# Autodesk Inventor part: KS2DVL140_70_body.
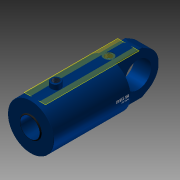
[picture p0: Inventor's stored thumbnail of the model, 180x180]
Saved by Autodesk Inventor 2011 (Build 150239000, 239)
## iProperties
Created: 2010-11
Document SubType Name: Modeling
Designer: TB
Mass: 405.061 g
Surface Area: 916.939 cm^2
Volume: 405.061 cm^3
Density: 1 g/cm^3
Author: TB
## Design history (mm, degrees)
sketch "Sketch2"
  geometry: L1 (-35, -3)-(-35, 3); L2 (-35, -9)-(-35, 9); L3 (-35, 0)-(-35, 82.5); L4 (-35, 82.5)-(-313, 82.5); L5 (-313, 82.5)-(-313, 82.5); L6 (-313, 82.5)-(-328, 82.5); L7 (-328, 82.5)-(-328, 39); L8 (-328, 39)-(-331, 36); L9 (-331, 36)-(-331, 35); L10 (-331, 35)-(-218, 35); L11 (-218, 35)-(-218, 70); L12 (-218, 70)-(-66, 70); L13 (-66, 70)-(-66, 0); L14 (-66, 0)-(-35, 0); L15 (-66, 0)-(-148.421, 0); L16 (-35, 9)-(-32, 12) reference; L17 (-32, 12)-(-35, 12) reference; L18 (-35, 12)-(-35, 9) reference; L19 (-32, 12)-(-35, 9) reference; L20 (-32, 12)-(-35, 12) reference; L21 (-35, 9)-(-35, 12) reference; L22 (-35, 9)-(-32, 12) reference; 1 further point
  constraints: 44 end point, 8 perpendicular, 6 parallel, 5 collinear, 2 horizontal, 2 vertical, 1 coincident, 1 midpoint, 1 point on line, 10 other
  dimensions: "DiaY" = 165 diameter of L4 L15; "DiaI" = 140 diameter of L12 L15; "d4" = 1 distance of L8.end L9.end; "d5" = 45 deg angle of L10 L8; "d6" = 3 distance between parallel lines of L7 L9; "DiaStang" = 70 diameter of L10 L15; "RindDia" = 165 diameter of L6 L15; "RingLengde" = 15 distance of L5.end L6.end; "RingTykk" = 110 distance between parallel lines of L11 L7; "KroppLengde" = 293 distance between parallel lines of L7 L3 (derived); "BunnTykkelse" = 31 distance between parallel lines of L13 L3
revolve "Kropp" sketch "Sketch2" stored, may be unused: angle "d13" = 90 deg
sketch "Sketch3"
  geometry: L1 (-66, -70)-(-66, 70) reference; L2 (-66, 0.01)-(-166, 0.01); L3 (-166, -0.01)-(-66, -0.01); A1 r 0.01 centre (-166, 0) between (-166, 0.01) and (-166, -0.01); A2 r 0.01 centre (-66, 0) between (-66, -0.01) and (-66, 0.01); 2 further points
  constraints: 4 end point, 4 point on circle, 4 tangent, 2 centre point, 1 coincident, 1 midpoint, 1 parallel, 1 perpendicular
  dimensions: "d17" = 0.01 radius of A2; "d18" = 100 distance of L2.start L2.end (= Slaglengde)
feature "BaneTransitionalConstraint" sketch "Sketch3" dims "d19" = 2, "d20" = 0
sketch "Sketch6"
  geometry: L1 (-115.5, 0)-(115.5, 0) reference; L2 (15.66, 81)-(-11.843, 81); L3 (82.5, 0)-(82.5, 31.248); L4 (-82.5, 0)-(-82.5, -18.451); A1 r 82.5 centre (0, 0) between (-82.5, 0) and (82.5, 0) reference; 2 further points
  constraints: 6 end point, 2 point on circle, 2 vertical, 2 other
  dimensions: "d30" = 81 distance from line of point (0, 0) L2 (computed from DiaY); "d31" = 0 deg angle of L1 L2 (computed from Vinkel_Plussport); "d37" = 90 deg angle of L2 L3; "d38" = 90 deg angle of L2 L4
  node "Projected Loop3"
workplane "Work Plane5"
sketch "Sketch7"
  geometry: L1 (15.66, -397.2)-(15.66, 66.2) reference; L2 (-19.633, -35)-(38.367, -35) reference; C1 r 17.5 at (15.66, -52.5); 1 further point
  constraints: 1 centre point, 1 point on line
  dimensions: "PortDia" = 35 diameter of C1
extrude "Extrusion2" cut sketch "Sketch7" stored distance "d34" = 1.5; taper "d35" = 0 deg
workplane "Work Plane7"
sketch "Sketch4"
  geometry: L1 (-16.68, -40)-(-16.68, -78.777); L2 (-16.68, -78.777)-(16.68, -78.777); L3 (16.68, -78.777)-(16.68, -40); L4 (16.68, -40)-(-16.68, -40); L5 (-40.643, -40)-(0, -40); L6 (-29, -35)-(29, -35); L7 (0, -35)-(0, -40); 2 further points
  constraints: 6 end point, 2 midpoint, 2 other
  dimensions: "d40" = 5 distance of L7.start L5.end
emboss "Emboss1" sketch "Sketch4" dims "d4" = 1, "d5" = 45 deg, "d6" = 3, "d22" = 0.2, "d23" = 0, "DiaI" = 140, "DiaY" = 165, "RindDia" = 165, "DiaStang" = 70, "RingTykk" = 110, "RingLengde" = 15, "KroppLengde" = 293 (derived), "BunnTykkelse" = 31
workplane "Work Plane8"
sketch "Sketch8"
  geometry: L1 (-29, -35)-(29, -35); L2 (0, -35)-(0, -40); L3 (-5.906, -110.587)-(-5.906, -40); L4 (-5.906, -40)-(5.906, -40); L5 (5.906, -40)-(5.906, -110.587); L6 (5.906, -110.587)-(-5.906, -110.587); L7 (82.5, -35)-(-82.5, -35); L8 (82.5, -35)-(-82.5, -35) reference; 3 further points
  constraints: 6 end point, 4 midpoint, 2 other
  dimensions: "d42" = 5 distance of L2.start L2.end
emboss "Emboss2" sketch "Sketch8" dims "d4" = 1, "d5" = 45 deg, "d6" = 3, "d43" = 0.2, "d44" = 0, "DiaI" = 140, "DiaY" = 165, "RindDia" = 165, "DiaStang" = 70, "RingTykk" = 110, "RingLengde" = 15, "KroppLengde" = 293 (derived), "BunnTykkelse" = 31
sketch "Sketch9"
  geometry: A1 r 12.5 centre (9.367, -52.5) between (0, -60.776) and (18.735, -60.776) reference; 1 further point
hole "Hole1" sketch "Sketch9" at (9.367, -52.5) diameter "d45" = 14.95; stored, may be unused: countersink angle "d49" = 82 deg, drill point angle "d51" = 118 deg; dims "d46" = 6, "d47" = 3.023, "d48" = 2, "DiaInvPluss" = 24.5
workplane "Work Plane9"
sketch "Sketch10"
  geometry: L1 (-115.5, 0)-(115.5, 0) reference; L2 (0, 82.5)-(13.136, 82.5); L3 (0, 82.5)-(0, 31.79); L4 (17.5, 80.623)-(17.5, 100); L5 (17.5, 100)-(0, 100); L6 (0, 100)-(0, 82.5); L7 (0, 82.5)-(17.5, 80.623); C1 r 82.5 at (0, 0) reference; A1 r 82.5 centre (0, 0) between (0, 82.5) and (17.5, 80.623); 1 further point
  constraints: 12 end point, 4 perpendicular, 2 concentric, 2 point on circle, 1 centre point, 1 point on line, 1 tangent
  dimensions: "d53" = 0 deg angle of L1 L2 (computed from Vinkel_Minusport); "DiaUtvStussMinus" = 35 diameter of L4 L3; "HøydeStussMinuss" = 17.5 distance between parallel lines of L2 L5
revolve "Revolution2" sketch "Sketch10" stored, may be unused: angle "d56" = 90 deg
hole "Hole2" diameter "d59" = 24.117; stored, may be unused: countersink angle "d63" = 82 deg, drill point angle "d65" = 118 deg; dims "d57" = 10, "d58" = 10, "d60" = 6, "d61" = 3.023, "d62" = 2, "DiaInvStussMinus" = 24.5
fillet "Fillet1" dims "d66" = 2
sketch "Sketch15"
  geometry: L1 (30, -76.852)-(30, 76.852); L2 (-30, -76.852)-(-30, 76.852); L3 (0, 115.5)-(0, -115.5) reference; A1 r 82.5 centre (0, 0) between (30, -76.852) and (-30, -76.852) reference; A2 r 82.5 centre (0, 0) between (30, 76.852) and (-30, 76.852); A3 r 82.5 centre (0, 0) between (-30, -76.852) and (30, -76.852)
  constraints: 8 point on circle, 4 end point, 4 point on line, 2 centre point, 2 concentric, 2 parallel, 1 coincident
  dimensions: "EyeBunnTykk" = 30 distance from line of L1 A1.centre; "EyeBunnTykk2" = 30 distance from line of A1.centre L2
extrude "Extrusion6" join sketch "Sketch15" taper "d98" = 0 deg; distance "LengdeEyeMinussBunntykk" = 153
sketch "Sketch16"
  geometry: L1 (-327, 82.5)-(118, 82.5) reference; L2 (-327, -82.5)-(118, -82.5) reference; L3 (-327, 82.5)-(118, 82.5) reference; L4 (118, 82.5)-(118, 76.852) reference; L5 (118, -76.852)-(118, 76.852) reference; L6 (-397.486, 0)-(221.915, 0) reference; L7 (43.5, 82.5)-(118, 82.5); L8 (118, 82.5)-(118, 8); A1 r 74.5 centre (43.5, 8) between (118, 8) and (43.5, 82.5); 6 further points; 2 other entities
  constraints: 4 end point, 4 tangent, 2 point on circle, 2 point on line, 1 centre point, 1 collinear, 1 perpendicular, 2 other
  dimensions: "d137" = 8 distance from line of L8.end L6
extrude "Extrusion7" cut sketch "Sketch16" taper "d102" = 0 deg; stored distance "ExtruEyeBunn" = 50
mirror "Mirror1"
sketch "Sketch20"
  geometry: L1 (-327, 82.5)-(118, 82.5) reference; L2 (118, -76.852)-(118, 76.852) reference; L3 (118, 82.5)-(118, 76.852) reference; L4 (-395.546, 0)-(210.279, 0) reference; L5 (-35, -76.852)-(-35, 76.852) reference; L6 (-35, 0)-(45, 0); L7 (45, 0)-(45, 20.918); L8 (56.067, 78.481)-(82.5, 63.22); A1 r 35 centre (43.843, 47.5) between (43.843, 82.5) and (43.843, 82.5); A2 r 30 centre (41.067, 52.5) between (56.067, 78.481) and (41.067, 82.5); A3 r 73 centre (46, 0) between (118, 12.042) and (82.5, 63.22); 3 further points
  constraints: 7 point on line, 6 end point, 6 point on circle, 4 tangent, 3 centre point, 1 coincident, 1 midpoint, 1 perpendicular
  dimensions: "d147" = 80 distance of L6.start L6.end; "d163" = 1 distance of point (46, 0) L6.end; "d165" = 73 radius of A3; "d166" = 30 deg angle of L1 L8; "d167" = 30 radius of A2
extrude "Extrusion10" cut sketch "Sketch20" stored distance "d144" = 10; taper "d145" = 0 deg
mirror "Mirror2"
sketch "Sketch17"
  geometry: L1 (153.704, 0)-(0, 0) reference; L2 (76.852, -385.8)-(76.852, 242.8) reference; C1 r 45.5 at (76.852, 80); 1 further point
  constraints: 1 centre point, 1 point on line
  dimensions: "DiaHullEyeBunn" = 91 diameter of C1; "d125" = 80 distance from line of C1.centre L1
extrude "Extrusion8" cut sketch "Sketch17" taper "d105" = 0 deg; distance "ExtruHullEye" = 60
pattern_circular "Circular Pattern1 Only Subsea" dims "d108" = 180 deg (derived)
workplane "Work Plane11"
sketch "Sketch18"
  geometry: L1 (0, -79.2)-(0, 13.2) reference; L2 (70, -66)-(-70, -66) reference; L3 (70, -66)-(-70, -66) reference; C1 r 17.5 at (0, -31); 1 further point
  constraints: 1 centre point
  dimensions: "DiaForsenkPlussPort" = 35 diameter of C1; "PlassPlussport" = 35 distance from line of L2 C1.centre
extrude "Extrusion9" cut sketch "Sketch18" stored distance "d113" = 10; taper "d114" = 0 deg
sketch "Sketch19"
  geometry: 10 further points
  constraints: 1 other
hole "Hole3" sketch "Sketch19" at (0, -31) diameter "d115" = 24.117; stored, may be unused: countersink angle "d119" = 90 deg, drill point angle "d121" = 118 deg; dims "d116" = 6, "d117" = 4, "d118" = 2, "d120" = 14.5
pattern_circular "Circular Pattern2 Only Subsea" dims angle "d123" = 360 deg
body "Solid1"
chamfer "Chamfer" distance "Chamfer" = 1; stored, may be unused: second distance "d15" = 2, angle "d16" = 45 deg
node "Projected Loop2"
body "Srf1"
node "Projected Loop10"
other parameters: "Slaglengde" = 100, "Forlengelse_rør" = 0, "Vinkel_Plussport" = 0 [user parameter; used in 1 equation term], "Vinkel_Minusport" = 0, "d32" = 90 deg, "d39" = 90 deg, "d41" = 90 deg, "PortMinusPlass" = -102, "Minusport2" = 180 deg, "ForsenkningPlussPort" = 80.7 (derived), "EyeLengdeUBunn" = 136, "d164" = 73
